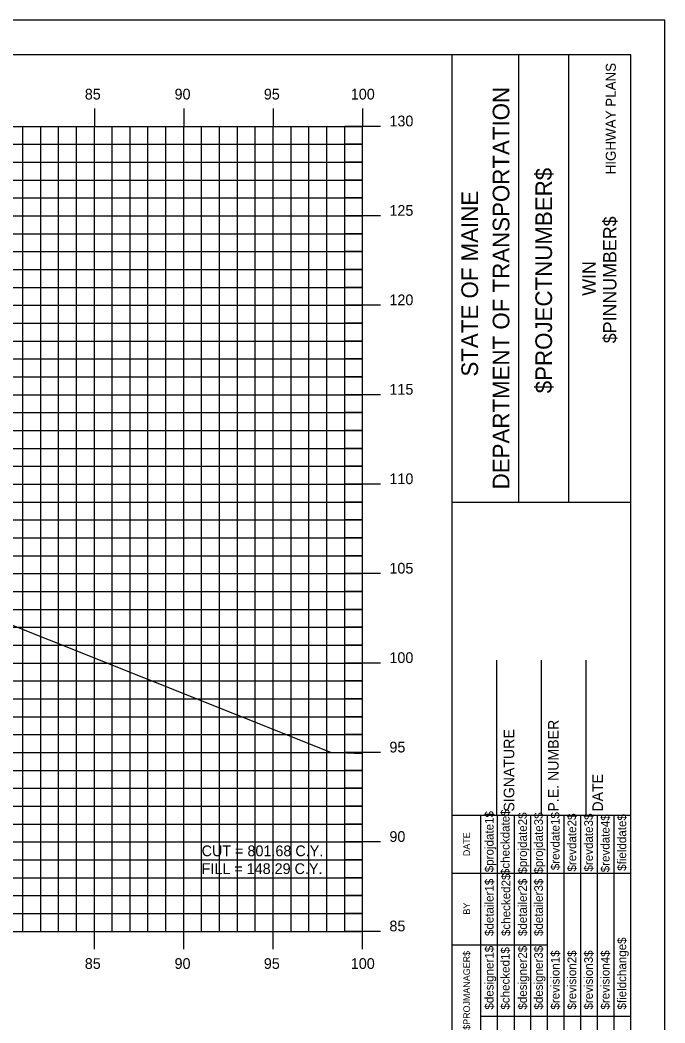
# Model space of a CAD drawing. Extents: x 850598 to 870284, y 366541 to 366651.
# Drawn here: x 852284 to 852320.1, y 366595.1 to 366651.2 of the extents above; entities that cross this region are included whole.
import ezdxf

# ---------------------------------------------------------------- set-up
doc = ezdxf.new("R2010")
doc.units = 0
for name, color, linetype in [('BORDER', 7, 'Continuous'), ('D_Text_Standard', 7, 'Continuous'), ('H_V ANNOTATION', 7, 'Continuous'), ('HIGHWAY_TITLE', 7, 'Continuous'), ('MAJOR', 7, 'Continuous'), ('MINOR', 7, 'Continuous'), ('PLOT BOUNDARY', 7, 'Continuous'), ('S_Roadway_Centerline', 7, 'Continuous')]:
    doc.layers.add(name, color=color, linetype=linetype)

msp = doc.modelspace()

# ---------------------------------------------------------------- linework, layer by layer
at = {"layer": 'BORDER'}
for p, q in [((852318.193, 366649.225), (852158.193, 366649.225)), ((852308.193, 366544.225), (852308.193, 366649.225)), ((852311.921, 366624.222), (852311.921, 366649.222)), ((852314.717, 366624.222), (852314.717, 366649.222)), ((852318.193, 366544.225), (852318.193, 366649.225)), ((852308.194, 366624.219), (852318.193, 366624.219)), ((852310.693, 366606.728), (852310.693, 366615.376)), ((852313.193, 366606.728), (852313.193, 366615.376)), ((852315.693, 366606.728), (852315.693, 366615.376)), ((852308.193, 366606.728), (852318.193, 366606.728))]:
    msp.add_line(p, q, dxfattribs=at)
for points in [[(852309.808, 366603.478), (852309.808, 366606.728)], [(852310.74, 366589.231), (852310.74, 366606.728)], [(852311.672, 366606.728), (852311.672, 366589.231)], [(852312.604, 366589.231), (852312.604, 366606.728)], [(852313.535, 366589.231), (852313.535, 366606.728)], [(852314.467, 366589.231), (852314.467, 366606.728)], [(852315.399, 366589.231), (852315.399, 366606.728)], [(852316.33, 366589.231), (852316.33, 366606.728)], [(852317.262, 366589.231), (852317.262, 366606.728)], [(852309.809, 366589.231), (852309.809, 366606.022)], [(852308.193, 366603.478), (852318.193, 366603.478)], [(852308.193, 366599.478), (852309.809, 366599.478)], [(852309.808, 366599.478), (852313.535, 366599.478)], [(852309.808, 366595.478), (852318.193, 366595.478)]]:
    msp.add_lwpolyline(points, dxfattribs=at)
at = {"layer": 'MAJOR'}
for p, q in [((852288.193, 366646.227), (852288.193, 366645.225)), ((852288.193, 366646.227), (852288.193, 366645.225)), ((852293.193, 366646.227), (852293.193, 366645.225)), ((852293.193, 366646.227), (852293.193, 366645.225)), ((852298.193, 366646.227), (852298.193, 366645.225)), ((852298.193, 366646.227), (852298.193, 366645.225)), ((852303.193, 366646.227), (852303.193, 366645.225)), ((852303.193, 366646.227), (852303.193, 366645.225)), ((852163.193, 366645.225), (852303.193, 366645.225)), ((852163.193, 366645.225), (852303.193, 366645.225)), ((852163.193, 366645.225), (852303.193, 366645.225)), ((852163.193, 366645.225), (852303.193, 366645.225)), ((852288.193, 366600.225), (852288.193, 366645.225)), ((852288.193, 366600.225), (852288.193, 366645.225)), ((852293.193, 366600.225), (852293.193, 366645.225)), ((852293.193, 366600.225), (852293.193, 366645.225)), ((852298.193, 366600.225), (852298.193, 366645.225)), ((852298.193, 366600.225), (852298.193, 366645.225)), ((852304.195, 366645.225), (852302.191, 366645.225)), ((852304.195, 366645.225), (852302.191, 366645.225)), ((852303.193, 366600.225), (852303.193, 366645.225)), ((852303.193, 366600.225), (852303.193, 366645.225)), ((852303.193, 366600.225), (852303.193, 366645.225)), ((852303.193, 366600.225), (852303.193, 366645.225)), ((852163.193, 366640.225), (852303.193, 366640.225)), ((852163.193, 366640.225), (852303.193, 366640.225)), ((852304.195, 366640.225), (852302.191, 366640.225)), ((852304.195, 366640.225), (852302.191, 366640.225)), ((852163.193, 366635.225), (852303.193, 366635.225)), ((852163.193, 366635.225), (852303.193, 366635.225)), ((852304.195, 366635.225), (852302.191, 366635.225)), ((852304.195, 366635.225), (852302.191, 366635.225)), ((852163.193, 366630.225), (852303.193, 366630.225)), ((852163.193, 366630.225), (852303.193, 366630.225)), ((852304.195, 366630.225), (852302.191, 366630.225)), ((852304.195, 366630.225), (852302.191, 366630.225)), ((852163.193, 366625.225), (852303.193, 366625.225)), ((852163.193, 366625.225), (852303.193, 366625.225)), ((852304.195, 366625.225), (852302.191, 366625.225)), ((852304.195, 366625.225), (852302.191, 366625.225)), ((852163.193, 366620.225), (852303.193, 366620.225)), ((852163.193, 366620.225), (852303.193, 366620.225)), ((852304.195, 366620.225), (852302.191, 366620.225)), ((852304.195, 366620.225), (852302.191, 366620.225)), ((852163.193, 366615.225), (852303.193, 366615.225)), ((852163.193, 366615.225), (852303.193, 366615.225)), ((852304.195, 366615.225), (852302.191, 366615.225)), ((852304.195, 366615.225), (852302.191, 366615.225)), ((852163.193, 366610.225), (852303.193, 366610.225)), ((852163.193, 366610.225), (852303.193, 366610.225)), ((852304.195, 366610.225), (852302.191, 366610.225)), ((852304.195, 366610.225), (852302.191, 366610.225)), ((852163.193, 366605.225), (852303.193, 366605.225)), ((852163.193, 366605.225), (852303.193, 366605.225)), ((852304.195, 366605.225), (852302.191, 366605.225)), ((852304.195, 366605.225), (852302.191, 366605.225)), ((852163.193, 366600.225), (852303.193, 366600.225)), ((852163.193, 366600.225), (852303.193, 366600.225)), ((852163.193, 366600.225), (852303.193, 366600.225)), ((852163.193, 366600.225), (852303.193, 366600.225)), ((852288.193, 366599.223), (852288.193, 366600.225)), ((852288.193, 366599.223), (852288.193, 366600.225)), ((852293.193, 366599.223), (852293.193, 366600.225)), ((852293.193, 366599.223), (852293.193, 366600.225)), ((852298.193, 366599.223), (852298.193, 366600.225)), ((852298.193, 366599.223), (852298.193, 366600.225)), ((852304.195, 366600.225), (852302.191, 366600.225)), ((852304.195, 366600.225), (852302.191, 366600.225)), ((852303.193, 366599.223), (852303.193, 366600.225)), ((852303.193, 366599.223), (852303.193, 366600.225))]:
    msp.add_line(p, q, dxfattribs=at)
at = {"layer": 'MINOR'}
for p, q in [((852284.193, 366600.225), (852284.193, 366645.225)), ((852284.193, 366600.225), (852284.193, 366645.225)), ((852285.193, 366600.225), (852285.193, 366645.225)), ((852285.193, 366600.225), (852285.193, 366645.225)), ((852286.193, 366600.225), (852286.193, 366645.225)), ((852286.193, 366600.225), (852286.193, 366645.225)), ((852287.193, 366600.225), (852287.193, 366645.225)), ((852287.193, 366600.225), (852287.193, 366645.225)), ((852289.193, 366600.225), (852289.193, 366645.225)), ((852289.193, 366600.225), (852289.193, 366645.225)), ((852290.193, 366600.225), (852290.193, 366645.225)), ((852290.193, 366600.225), (852290.193, 366645.225)), ((852291.193, 366600.225), (852291.193, 366645.225)), ((852291.193, 366600.225), (852291.193, 366645.225)), ((852292.193, 366600.225), (852292.193, 366645.225)), ((852292.193, 366600.225), (852292.193, 366645.225)), ((852294.193, 366600.225), (852294.193, 366645.225)), ((852294.193, 366600.225), (852294.193, 366645.225)), ((852295.193, 366600.225), (852295.193, 366645.225)), ((852295.193, 366600.225), (852295.193, 366645.225)), ((852296.193, 366600.225), (852296.193, 366645.225)), ((852296.193, 366600.225), (852296.193, 366645.225)), ((852297.193, 366600.225), (852297.193, 366645.225)), ((852297.193, 366600.225), (852297.193, 366645.225)), ((852299.193, 366600.225), (852299.193, 366645.225)), ((852299.193, 366600.225), (852299.193, 366645.225)), ((852300.193, 366600.225), (852300.193, 366645.225)), ((852300.193, 366600.225), (852300.193, 366645.225)), ((852301.193, 366600.225), (852301.193, 366645.225)), ((852301.193, 366600.225), (852301.193, 366645.225)), ((852302.193, 366600.225), (852302.193, 366645.225)), ((852302.193, 366600.225), (852302.193, 366645.225)), ((852163.193, 366644.225), (852303.193, 366644.225)), ((852163.193, 366644.225), (852303.193, 366644.225)), ((852303.193, 366644.225), (852302.191, 366644.225)), ((852303.193, 366644.225), (852302.191, 366644.225)), ((852163.193, 366643.225), (852303.193, 366643.225)), ((852163.193, 366643.225), (852303.193, 366643.225)), ((852303.193, 366643.225), (852302.191, 366643.225)), ((852303.193, 366643.225), (852302.191, 366643.225)), ((852163.193, 366642.225), (852303.193, 366642.225)), ((852163.193, 366642.225), (852303.193, 366642.225)), ((852303.193, 366642.225), (852302.191, 366642.225)), ((852303.193, 366642.225), (852302.191, 366642.225)), ((852163.193, 366641.225), (852303.193, 366641.225)), ((852163.193, 366641.225), (852303.193, 366641.225)), ((852303.193, 366641.225), (852302.191, 366641.225)), ((852303.193, 366641.225), (852302.191, 366641.225)), ((852163.193, 366639.225), (852303.193, 366639.225)), ((852163.193, 366639.225), (852303.193, 366639.225)), ((852303.193, 366639.225), (852302.191, 366639.225)), ((852303.193, 366639.225), (852302.191, 366639.225)), ((852163.193, 366638.225), (852303.193, 366638.225)), ((852163.193, 366638.225), (852303.193, 366638.225)), ((852303.193, 366638.225), (852302.191, 366638.225)), ((852303.193, 366638.225), (852302.191, 366638.225)), ((852163.193, 366637.225), (852303.193, 366637.225)), ((852163.193, 366637.225), (852303.193, 366637.225)), ((852303.193, 366637.225), (852302.191, 366637.225)), ((852303.193, 366637.225), (852302.191, 366637.225)), ((852163.193, 366636.225), (852303.193, 366636.225)), ((852163.193, 366636.225), (852303.193, 366636.225)), ((852303.193, 366636.225), (852302.191, 366636.225)), ((852303.193, 366636.225), (852302.191, 366636.225)), ((852163.193, 366634.225), (852303.193, 366634.225)), ((852163.193, 366634.225), (852303.193, 366634.225)), ((852303.193, 366634.225), (852302.191, 366634.225)), ((852303.193, 366634.225), (852302.191, 366634.225)), ((852163.193, 366633.225), (852303.193, 366633.225)), ((852163.193, 366633.225), (852303.193, 366633.225)), ((852303.193, 366633.225), (852302.191, 366633.225)), ((852303.193, 366633.225), (852302.191, 366633.225)), ((852163.193, 366632.225), (852303.193, 366632.225)), ((852163.193, 366632.225), (852303.193, 366632.225)), ((852303.193, 366632.225), (852302.191, 366632.225)), ((852303.193, 366632.225), (852302.191, 366632.225)), ((852163.193, 366631.225), (852303.193, 366631.225)), ((852163.193, 366631.225), (852303.193, 366631.225)), ((852303.193, 366631.225), (852302.191, 366631.225)), ((852303.193, 366631.225), (852302.191, 366631.225)), ((852163.193, 366629.225), (852303.193, 366629.225)), ((852163.193, 366629.225), (852303.193, 366629.225)), ((852303.193, 366629.225), (852302.191, 366629.225)), ((852303.193, 366629.225), (852302.191, 366629.225)), ((852163.193, 366628.225), (852303.193, 366628.225)), ((852163.193, 366628.225), (852303.193, 366628.225)), ((852303.193, 366628.225), (852302.191, 366628.225)), ((852303.193, 366628.225), (852302.191, 366628.225)), ((852163.193, 366627.225), (852303.193, 366627.225)), ((852163.193, 366627.225), (852303.193, 366627.225)), ((852303.193, 366627.225), (852302.191, 366627.225)), ((852303.193, 366627.225), (852302.191, 366627.225)), ((852163.193, 366626.225), (852303.193, 366626.225)), ((852163.193, 366626.225), (852303.193, 366626.225)), ((852303.193, 366626.225), (852302.191, 366626.225)), ((852303.193, 366626.225), (852302.191, 366626.225)), ((852163.193, 366624.225), (852303.193, 366624.225)), ((852163.193, 366624.225), (852303.193, 366624.225)), ((852303.193, 366624.225), (852302.191, 366624.225)), ((852303.193, 366624.225), (852302.191, 366624.225)), ((852163.193, 366623.225), (852303.193, 366623.225)), ((852163.193, 366623.225), (852303.193, 366623.225)), ((852303.193, 366623.225), (852302.191, 366623.225)), ((852303.193, 366623.225), (852302.191, 366623.225)), ((852163.193, 366622.225), (852303.193, 366622.225)), ((852163.193, 366622.225), (852303.193, 366622.225)), ((852303.193, 366622.225), (852302.191, 366622.225)), ((852303.193, 366622.225), (852302.191, 366622.225)), ((852163.193, 366621.225), (852303.193, 366621.225)), ((852163.193, 366621.225), (852303.193, 366621.225)), ((852303.193, 366621.225), (852302.191, 366621.225)), ((852303.193, 366621.225), (852302.191, 366621.225)), ((852163.193, 366619.225), (852303.193, 366619.225)), ((852163.193, 366619.225), (852303.193, 366619.225)), ((852303.193, 366619.225), (852302.191, 366619.225)), ((852303.193, 366619.225), (852302.191, 366619.225)), ((852163.193, 366618.225), (852303.193, 366618.225)), ((852163.193, 366618.225), (852303.193, 366618.225)), ((852303.193, 366618.225), (852302.191, 366618.225)), ((852303.193, 366618.225), (852302.191, 366618.225)), ((852163.193, 366617.225), (852303.193, 366617.225)), ((852163.193, 366617.225), (852303.193, 366617.225)), ((852303.193, 366617.225), (852302.191, 366617.225)), ((852303.193, 366617.225), (852302.191, 366617.225)), ((852163.193, 366616.225), (852303.193, 366616.225)), ((852163.193, 366616.225), (852303.193, 366616.225)), ((852303.193, 366616.225), (852302.191, 366616.225)), ((852303.193, 366616.225), (852302.191, 366616.225)), ((852163.193, 366614.225), (852303.193, 366614.225)), ((852163.193, 366614.225), (852303.193, 366614.225)), ((852303.193, 366614.225), (852302.191, 366614.225)), ((852303.193, 366614.225), (852302.191, 366614.225)), ((852163.193, 366613.225), (852303.193, 366613.225)), ((852163.193, 366613.225), (852303.193, 366613.225)), ((852303.193, 366613.225), (852302.191, 366613.225)), ((852303.193, 366613.225), (852302.191, 366613.225)), ((852163.193, 366612.225), (852303.193, 366612.225)), ((852163.193, 366612.225), (852303.193, 366612.225)), ((852303.193, 366612.225), (852302.191, 366612.225)), ((852303.193, 366612.225), (852302.191, 366612.225)), ((852163.193, 366611.225), (852303.193, 366611.225)), ((852163.193, 366611.225), (852303.193, 366611.225)), ((852303.193, 366611.225), (852302.191, 366611.225)), ((852303.193, 366611.225), (852302.191, 366611.225)), ((852163.193, 366609.225), (852303.193, 366609.225)), ((852163.193, 366609.225), (852303.193, 366609.225)), ((852303.193, 366609.225), (852302.191, 366609.225)), ((852303.193, 366609.225), (852302.191, 366609.225)), ((852163.193, 366608.225), (852303.193, 366608.225)), ((852163.193, 366608.225), (852303.193, 366608.225)), ((852303.193, 366608.225), (852302.191, 366608.225)), ((852303.193, 366608.225), (852302.191, 366608.225)), ((852163.193, 366607.225), (852303.193, 366607.225)), ((852163.193, 366607.225), (852303.193, 366607.225)), ((852303.193, 366607.225), (852302.191, 366607.225)), ((852303.193, 366607.225), (852302.191, 366607.225)), ((852163.193, 366606.225), (852303.193, 366606.225)), ((852163.193, 366606.225), (852303.193, 366606.225)), ((852303.193, 366606.225), (852302.191, 366606.225)), ((852303.193, 366606.225), (852302.191, 366606.225)), ((852163.193, 366604.225), (852303.193, 366604.225)), ((852163.193, 366604.225), (852303.193, 366604.225)), ((852303.193, 366604.225), (852302.191, 366604.225)), ((852303.193, 366604.225), (852302.191, 366604.225)), ((852163.193, 366603.225), (852303.193, 366603.225)), ((852163.193, 366603.225), (852303.193, 366603.225)), ((852303.193, 366603.225), (852302.191, 366603.225)), ((852303.193, 366603.225), (852302.191, 366603.225)), ((852163.193, 366602.225), (852303.193, 366602.225)), ((852163.193, 366602.225), (852303.193, 366602.225)), ((852303.193, 366602.225), (852302.191, 366602.225)), ((852303.193, 366602.225), (852302.191, 366602.225)), ((852163.193, 366601.225), (852303.193, 366601.225)), ((852163.193, 366601.225), (852303.193, 366601.225)), ((852303.193, 366601.225), (852302.191, 366601.225)), ((852303.193, 366601.225), (852302.191, 366601.225))]:
    msp.add_line(p, q, dxfattribs=at)
at = {"layer": 'PLOT BOUNDARY'}
msp.add_lwpolyline([(852150.1, 366541.166), (852320.1, 366541.166), (852320.1, 366651.166), (852150.1, 366651.166)], close=True, dxfattribs=at)
at = {"layer": 'S_Roadway_Centerline'}
msp.add_lwpolyline([(852163.193, 366629.821), (852169.749, 366629.755), (852192.19, 366630.833), (852213.344, 366631.869), (852218.98, 366632.668), (852221.58, 366633.055), (852222.854, 366633.212), (852226.268, 366633.657), (852233.105, 366634.034), (852240.803, 366634.416), (852251.826, 366634.342), (852257.286, 366634.316), (852257.632, 366634.226), (852260.282, 366632.914), (852271.613, 366622.89), (852272.519, 366622.087), (852273.262, 366621.508), (852273.925, 366621.154), (852275.185, 366620.695), (852301.398, 366610.239), (852303.193, 366610.163)], dxfattribs=at)

# ---------------------------------------------------------------- texts
at = {"layer": 'BORDER'}
for s, height, p in [('DEPARTMENT OF TRANSPORTATION', 0.93176, (852311.4, 366624.931)), ('$PROJECTNUMBER$', 0.93176, (852313.785, 366630.304)), ('STATE OF MAINE', 0.93176, (852309.648, 366631.237)), ('$PINNUMBER$', 0.74527, (852317.388, 366633.1)), ('WIN', 0.7453, (852316.23, 366635.755)), ('SIGNATURE', 0.5906, (852311.673, 366606.92)), ('P.E. NUMBER', 0.59055, (852314.154, 366606.92)), ('DATE', 0.5906, (852316.634, 366606.92)), ('$checkdate$', 0.48455, (852311.41, 366603.371)), ('$projdate1$', 0.48455, (852310.516, 366603.529)), ('$projdate2$', 0.48455, (852312.379, 366603.45)), ('$projdate3$', 0.48455, (852313.274, 366603.45)), ('$revdate1$', 0.4845, (852314.205, 366603.647)), ('$revdate2$', 0.4845, (852315.137, 366603.568)), ('$revdate3$', 0.4845, (852316.069, 366603.568)), ('$revdate4$', 0.4845, (852317, 366603.529)), ('$fielddate$', 0.48455, (852317.932, 366603.607)), ('DATE', 0.3714, (852309.197, 366604.434)), ('$detailer1$', 0.48455, (852310.516, 366599.963)), ('$checked2$', 0.4845, (852311.448, 366599.963)), ('$detailer2$', 0.48455, (852312.379, 366599.963)), ('$detailer3$', 0.48455, (852313.274, 366599.963)), ('BY', 0.3714, (852309.197, 366601.163)), ('$fieldchange$', 0.48455, (852317.932, 366595.851)), ('$designer1$', 0.48455, (852310.516, 366595.851)), ('$checked1$', 0.4845, (852311.41, 366595.851)), ('$designer2$', 0.48455, (852312.379, 366595.851)), ('$designer3$', 0.48455, (852313.274, 366595.851)), ('$revision1$', 0.48455, (852314.205, 366595.851)), ('$revision2$', 0.48455, (852315.137, 366595.851)), ('$revision3$', 0.48455, (852316.069, 366595.851)), ('$revision4$', 0.48455, (852317, 366595.851)), ('$PROJMANAGER$', 0.37275, (852309.197, 366594.723))]:
    msp.add_text(s, height=height, rotation=90, dxfattribs=at).set_placement(p)
at = {"layer": 'D_Text_Standard'}
for s, p in [('CUT = 801.68 C.Y.', (852294.193, 366604.425)), ('FILL = 148.29 C.Y.', (852294.193, 366603.429))]:
    msp.add_text(s, height=0.6, dxfattribs=at).set_placement(p)
at = {"layer": 'H_V ANNOTATION'}
for s, p in [('85', (852287.66, 366646.725)), ('90', (852292.679, 366646.725)), ('95', (852297.671, 366646.725)), ('100', (852302.534, 366646.725)), ('130', (852304.693, 366645.225)), ('125', (852304.693, 366640.225)), ('120', (852304.693, 366635.225)), ('115', (852304.693, 366630.225)), ('110', (852304.693, 366625.225)), ('105', (852304.693, 366620.225)), ('100', (852304.693, 366615.225)), ('95', (852304.693, 366610.225)), ('90', (852304.693, 366605.225)), ('85', (852304.693, 366600.225)), ('85', (852287.66, 366598.125)), ('90', (852292.679, 366598.125)), ('95', (852297.671, 366598.125)), ('100', (852302.534, 366598.125))]:
    msp.add_text(s, height=0.6, dxfattribs=at).set_placement(p)
at = {"layer": 'HIGHWAY_TITLE'}
msp.add_text('HIGHWAY PLANS', height=0.55901, rotation=90, dxfattribs=at).set_placement((852317.351, 366642.541))

doc.saveas('drawing.dxf')
